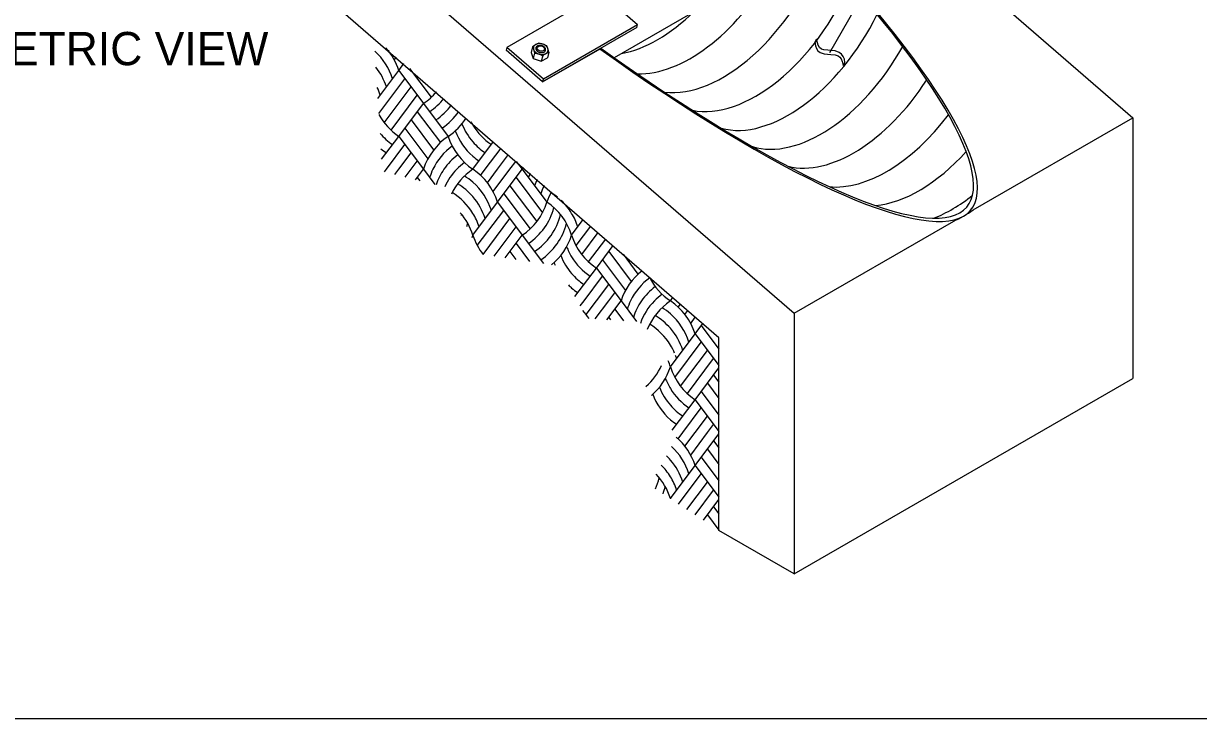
# Model space of a CAD drawing. Extents: x 99862 to 103151, y 100000 to 102076.
# Drawn here: x 101841 to 102547, y 100000 to 100418 of the extents above; entities that cross this region are included whole.
import ezdxf

# ---------------------------------------------------------------- set-up
doc = ezdxf.new("R2010")
doc.units = 0
for name, color, linetype in [('Level 1', 7, 'Continuous'), ('Level 15', 7, 'Continuous'), ('Level 20', 7, 'Continuous'), ('Level 30', 7, 'Continuous'), ('Level 9', 7, 'Continuous')]:
    doc.layers.add(name, color=color, linetype=linetype)

msp = doc.modelspace()

# ---------------------------------------------------------------- linework, layer by layer
at = {"layer": 'Level 1'}
for p, q in [((101553.78, 100893.22), (102304.36, 100243.2)), ((102259.1, 100228.52), (101542.8, 100848.86)), ((101988.26, 100810.88), (102508.01, 100360.77)), ((102296.76, 100455.02), (102196.14, 100396.92)), ((102188.14, 100435.77), (102131.57, 100403.11)), ((102210.09, 100416.76), (102188.14, 100435.77)), ((102209.66, 100415.03), (102153.09, 100382.37)), ((102210.09, 100416.76), (102153.52, 100384.1)), ((102209.66, 100415.03), (102210.09, 100416.76)), ((102131.57, 100403.11), (102131.14, 100401.38)), ((102153.09, 100382.37), (102131.14, 100401.38)), ((102153.52, 100384.1), (102131.57, 100403.11)), ((102153.09, 100382.37), (102187.6, 100402.29)), ((102153.09, 100382.37), (102153.52, 100384.1)), ((102412.04, 100305.37), (102508.01, 100360.77)), ((102508.01, 100360.77), (102508.01, 100204.01)), ((102304.36, 100243.2), (102400.33, 100298.6)), ((102304.36, 100243.2), (102304.36, 100086.43)), ((102259.1, 100112.56), (102259.1, 100228.52)), ((102304.36, 100086.43), (102508.01, 100204.01)), ((102304.36, 100086.43), (102259.1, 100112.56))]:
    msp.add_line(p, q, dxfattribs=at)
msp.add_lwpolyline([(99862, 99999.5), (103151, 99999.5), (103151, 102075.5), (99862, 102075.5)], close=True, dxfattribs=at)
for centre, major_axis, ratio, start_param, end_param in [((102135.04, 100536.62), (275.44, -231.36), 0.205372, 5.072059, 7.345323), ((102135.04, 100536.62), (273.14, -229.43), 0.205372, 5.075959, 7.341423), ((102406.18, 100380.08), (-48, -83.14), 0.57735, 0.69904, 0.871756)]:
    msp.add_ellipse(centre, major_axis=major_axis, ratio=ratio, start_param=start_param, end_param=end_param, dxfattribs=at)
at = {"layer": 'Level 15'}
msp.add_line((102325.74, 100400.11), (102401.81, 100531.87), dxfattribs=at)
at = {"layer": 'Level 20'}
for p, q in [((102316.68, 100406.19), (102317.05, 100404.07)), ((102317.74, 100408.02), (102316.69, 100406.19)), ((102318.72, 100404.46), (102317.74, 100408.02)), ((102319.6, 100403.06), (102318.72, 100404.46)), ((102060.46, 100400.86), (102060.71, 100401.2)), ((102063.9, 100395.55), (102065.21, 100397.29)), ((102317.05, 100404.07), (102317.69, 100402.42)), ((102317.69, 100402.42), (102318.65, 100401.11)), ((102318.65, 100401.11), (102319.97, 100400.11)), ((102320.68, 100402.14), (102319.6, 100403.06)), ((102319.97, 100400.11), (102322.27, 100399.22)), ((102322.08, 100401.61), (102320.68, 100402.14)), ((102324.5, 100401.41), (102322.08, 100401.61)), ((102322.27, 100399.22), (102326.35, 100398.95)), ((102328.9, 100401.03), (102324.5, 100401.41)), ((102326.35, 100398.95), (102328.89, 100398.73)), ((102328.89, 100398.73), (102330.71, 100398.09)), ((102331.45, 100400.11), (102328.9, 100401.03)), ((102330.71, 100398.09), (102331.76, 100397.27)), ((102332.85, 100399.03), (102331.45, 100400.11)), ((102331.76, 100397.27), (102332.56, 100396.18)), ((102333.87, 100397.66), (102332.85, 100399.03)), ((102334.5, 100395.99), (102333.87, 100397.66)), ((102066.58, 100389.22), (102069.7, 100393.38)), ((102073.11, 100390.41), (102086.08, 100373.11)), ((102332.56, 100396.18), (102333.18, 100394.55)), ((102333.18, 100394.55), (102333.7, 100392.19)), ((102333.7, 100392.19), (102334.76, 100394.02)), ((102334.76, 100394.02), (102334.5, 100395.99)), ((102053.99, 100372.43), (102066.58, 100389.22)), ((102054.55, 100363.29), (102070.29, 100384.27)), ((102066.58, 100389.22), (102081.43, 100369.42)), ((102057.85, 100357.78), (102074, 100379.32)), ((102061.92, 100353.32), (102077.72, 100374.37)), ((102066.58, 100349.62), (102081.43, 100369.42)), ((102081.43, 100369.42), (102096.28, 100349.62)), ((102077.72, 100364.47), (102091.62, 100345.93)), ((102074, 100359.52), (102087.55, 100341.46)), ((102056.25, 100335.85), (102066.58, 100349.62)), ((102066.58, 100349.62), (102081.43, 100329.82)), ((102070.29, 100354.57), (102084.1, 100336.16)), ((102059.15, 100329.82), (102070.29, 100344.67)), ((102111.13, 100329.82), (102123.6, 100346.46)), ((102118.55, 100329.82), (102128.1, 100342.55)), ((102066.58, 100329.82), (102074, 100339.72)), ((102074, 100329.82), (102077.72, 100334.77)), ((102125.97, 100329.82), (102132.59, 100338.64)), ((102133.4, 100329.82), (102137.08, 100334.73)), ((102137.26, 100334.58), (102140.82, 100329.82)), ((102057.96, 100328.22), (102059.15, 100329.82)), ((102064.21, 100326.66), (102066.58, 100329.82)), ((102070.46, 100325.1), (102074, 100329.82)), ((102076.71, 100323.54), (102081.43, 100329.82)), ((102081.43, 100329.82), (102088.32, 100320.63)), ((102115.78, 100326.13), (102118.55, 100329.82)), ((102119.86, 100321.67), (102125.97, 100329.82)), ((102123.3, 100316.36), (102133.4, 100329.82)), ((102125.97, 100310.02), (102140.82, 100329.82)), ((102140.82, 100329.82), (102155.67, 100310.02)), ((102077.72, 100324.87), (102079.18, 100322.92)), ((102133.4, 100319.92), (102149.56, 100298.38)), ((102137.11, 100324.87), (102153, 100303.69)), ((102129.69, 100314.97), (102145.48, 100293.92)), ((102111.13, 100290.22), (102125.97, 100310.02)), ((102125.97, 100310.02), (102140.82, 100290.22)), ((102113.8, 100283.89), (102129.69, 100305.07)), ((102117.24, 100278.58), (102133.4, 100300.12)), ((102170.52, 100290.22), (102177.51, 100299.54)), ((102123.92, 100277.58), (102137.11, 100295.17)), ((102173.2, 100283.89), (102182, 100295.63)), ((102176.64, 100278.58), (102186.49, 100291.72)), ((102130.59, 100276.59), (102140.82, 100290.22)), ((102137.11, 100285.27), (102145.27, 100274.4)), ((102140.82, 100290.22), (102153.63, 100273.16)), ((102180.72, 100274.12), (102190.99, 100287.81)), ((102133.4, 100280.33), (102136.91, 100275.64)), ((102185.37, 100270.43), (102195.48, 100283.9)), ((102192.8, 100280.33), (102206.34, 100262.27)), ((102201.41, 100278.74), (102210.41, 100266.73)), ((102172.5, 100253.27), (102185.37, 100270.43)), ((102185.37, 100270.43), (102200.22, 100250.63)), ((102189.08, 100275.38), (102202.89, 100256.96)), ((102177.95, 100250.63), (102189.08, 100265.48)), ((102185.37, 100250.63), (102192.8, 100260.53)), ((102175.68, 100247.61), (102177.95, 100250.63)), ((102179.25, 100242.47), (102185.37, 100250.63)), ((102184.68, 100239.8), (102192.8, 100250.63)), ((102191.76, 100239.35), (102200.22, 100250.63)), ((102192.8, 100250.63), (102196.51, 100255.58)), ((102200.22, 100250.63), (102209.54, 100238.2)), ((102229.92, 100250.63), (102231.42, 100252.62)), ((102234.57, 100246.93), (102235.91, 100248.71)), ((102196.51, 100245.68), (102201.74, 100238.7)), ((102238.65, 100242.47), (102240.4, 100244.8)), ((102192.8, 100240.73), (102193.94, 100239.21)), ((102242.09, 100237.16), (102244.89, 100240.89)), ((102244.77, 100230.83), (102249.38, 100236.98)), ((102248.48, 100235.78), (102259.1, 100221.61)), ((102229.92, 100211.03), (102244.77, 100230.83)), ((102244.77, 100230.83), (102259.1, 100211.71)), ((102232.59, 100204.69), (102248.48, 100225.88)), ((102236.04, 100199.39), (102252.19, 100220.93)), ((102240.11, 100194.92), (102255.9, 100215.98)), ((102244.77, 100191.23), (102259.1, 100210.35)), ((102252.19, 100201.13), (102259.1, 100191.91)), ((102255.9, 100206.08), (102259.1, 100201.81)), ((102248.48, 100196.18), (102259.1, 100182.01)), ((102230.99, 100172.85), (102244.77, 100191.23)), ((102237.34, 100171.43), (102248.48, 100186.28)), ((102244.77, 100191.23), (102259.1, 100172.11)), ((102244.77, 100171.43), (102252.19, 100181.33)), ((102234.57, 100167.74), (102237.34, 100171.43)), ((102238.65, 100163.27), (102244.77, 100171.43)), ((102242.09, 100157.97), (102252.19, 100171.43)), ((102252.19, 100171.43), (102255.9, 100176.38)), ((102244.77, 100151.63), (102259.1, 100170.75)), ((102255.9, 100166.48), (102259.1, 100162.21)), ((102252.19, 100161.53), (102259.1, 100152.31)), ((102229.92, 100131.83), (102244.77, 100151.63)), ((102244.77, 100151.63), (102259.1, 100132.52)), ((102248.48, 100156.58), (102259.1, 100142.42)), ((102234.83, 100128.49), (102248.48, 100146.68)), ((102239.81, 100125.22), (102252.19, 100141.73)), ((102244.78, 100121.96), (102255.9, 100136.78)), ((102249.76, 100118.69), (102259.1, 100131.15)), ((102252.19, 100121.93), (102259.1, 100112.72)), ((102255.9, 100126.88), (102259.1, 100122.62))]:
    msp.add_line(p, q, dxfattribs=at)
for centre, start, end in [((102030.77, 100377.83), 56.09546, 56.09634), ((102030.77, 100377.83), 56.09229, 56.09546), ((102027.06, 100372.88), 17.6434, 47.92144), ((102030.77, 100377.83), 17.6434, 41.83649), ((102023.34, 100367.93), 17.6434, 38.31474), ((102019.63, 100362.98), 17.6434, 25.40054), ((102060.47, 100400.61), 303.90361, 319.88998), ((102064.18, 100395.66), 303.90361, 321.8678), ((102087.54, 100380.81), 208.72411, 236.09639), ((102067.89, 100390.71), 303.90361, 323.8491), ((102071.6, 100385.76), 303.90361, 325.83627), ((102075.32, 100380.81), 303.90361, 327.83178), ((102139.51, 100370.91), 201.43438, 220.94161), ((102143.22, 100375.86), 207.86012, 211.33197), ((102143.22, 100375.86), 211.33188, 236.09639), ((102083.83, 100375.86), 220.57668, 236.09639), ((102117.24, 100318.43), 123.90361, 162.3566), ((102132.09, 100361.01), 197.6434, 236.09639), ((102135.8, 100365.96), 200.24322, 228.95992), ((102080.11, 100370.91), 229.78728, 236.09639), ((102120.95, 100313.48), 126.30625, 154.2266), ((102139.51, 100370.91), 220.94154, 236.09639), ((102124.66, 100308.53), 127.1006, 145.49109), ((102128.37, 100303.58), 126.331, 135.71278), ((102135.8, 100365.96), 228.95986, 236.09639), ((102120.95, 100313.48), 154.22654, 162.3566), ((102124.66, 100308.53), 145.49102, 161.50024), ((102128.37, 100303.58), 135.71269, 155.49773), ((102132.09, 100298.63), 123.90361, 154.373), ((102090.16, 100298.63), 17.6434, 56.09634), ((102176.63, 100318.43), 160.30383, 162.3566), ((102180.35, 100313.48), 158.19633, 162.3566), ((102082.74, 100288.73), 40.94134, 59.30215), ((102086.45, 100293.68), 48.95968, 58.54646), ((102086.45, 100293.68), 17.6434, 48.95975), ((102184.06, 100308.53), 156.1156, 162.3566), ((102187.77, 100303.58), 154.05795, 162.3566), ((102079.03, 100283.78), 31.33163, 58.48737), ((102082.74, 100288.73), 17.6434, 40.94141), ((102191.48, 100298.63), 152.02004, 162.3566), ((102138.42, 100283.78), 51.29645, 58.48737), ((102119.86, 100321.41), 303.90361, 342.3566), ((102123.58, 100316.46), 303.90361, 345.01126), ((102134.71, 100278.84), 17.6434, 56.09639), ((102138.42, 100283.78), 31.33163, 46.63234), ((102075.32, 100278.84), 17.6434, 41.28523), ((102067.89, 100311.51), 345.51092, 346.31988), ((102079.03, 100283.78), 17.6434, 31.33172), ((102127.29, 100311.51), 303.90361, 346.31988), ((102138.42, 100283.78), 17.6434, 31.33172), ((102071.6, 100306.56), 342.67112, 345.77133), ((102131, 100306.56), 303.90361, 345.77133), ((102075.32, 100301.61), 339.97622, 342.3566), ((102146.94, 100301.61), 197.64354, 217.81866), ((102134.71, 100301.61), 309.08024, 342.3566), ((102206.33, 100301.61), 197.64354, 236.09639), ((102198.91, 100291.71), 201.43438, 220.94161), ((102202.62, 100296.66), 200.87781, 211.33197), ((102202.62, 100296.66), 211.33188, 236.09639), ((102195.2, 100286.76), 200.24322, 202.94034), ((102198.91, 100291.71), 220.94154, 236.09639), ((102236.03, 100239.24), 128.12232, 162.3566), ((102239.74, 100234.29), 126.30625, 154.2266), ((102250.88, 100281.81), 206.78548, 236.09639), ((102195.2, 100286.76), 224.90332, 228.95992), ((102195.19, 100286.76), 228.95986, 236.09639), ((102243.45, 100229.34), 127.1006, 145.49109), ((102239.74, 100234.29), 154.22654, 162.3566), ((102243.45, 100229.34), 145.49102, 162.3566), ((102247.17, 100224.39), 135.71269, 160.14728), ((102250.88, 100219.44), 123.90361, 158.03778), ((102247.17, 100224.39), 126.331, 135.71278), ((102208.96, 100219.44), 17.6434, 56.09634), ((102149.56, 100219.44), 33.2494, 42.59671), ((102201.53, 100209.54), 40.94134, 59.30215), ((102205.25, 100214.49), 48.95968, 58.54646), ((102205.24, 100214.49), 17.6434, 48.95975), ((102197.82, 100204.59), 31.33163, 58.48737), ((102201.53, 100209.54), 17.6434, 40.94141), ((102197.82, 100204.59), 22.93575, 31.33172), ((102194.11, 100199.64), 17.6434, 23.58804), ((102197.82, 100204.59), 17.6434, 20.65552), ((102190.4, 100227.37), 311.32441, 335.66285), ((102194.11, 100222.42), 310.33908, 342.3566), ((102265.73, 100222.42), 197.64354, 236.09639), ((102262.02, 100217.47), 200.87781, 211.33197), ((102254.59, 100207.57), 200.24322, 228.95992), ((102258.3, 100212.52), 201.43438, 220.94161), ((102262.01, 100217.47), 211.33188, 236.09639), ((102258.3, 100212.52), 220.94154, 236.09639), ((102254.59, 100207.57), 228.95986, 236.09639), ((102208.96, 100140.24), 17.6434, 49.3061), ((102201.53, 100130.34), 40.94134, 46.36292), ((102205.24, 100135.29), 17.6434, 47.71239), ((102197.82, 100125.39), 31.33163, 45.00368), ((102201.53, 100130.34), 17.6434, 40.94141), ((102186.68, 100153.12), 335.63908, 346.31988), ((102194.11, 100120.44), 17.6434, 43.63506), ((102197.82, 100125.39), 17.6434, 31.33172), ((102190.4, 100148.17), 338.89825, 345.77133), ((102194.11, 100143.22), 342.19797, 342.3566), ((102265.73, 100143.22), 197.64354, 197.88516)]:
    msp.add_arc(centre, 37.58, start, end, dxfattribs=at)
at = {"layer": 'Level 30'}
for centre, start_param, end_param in [((102261.61, 100463.55), 0.240997, 1.861824), ((102241.95, 100474.9), 0.295282, 1.581599), ((102281.26, 100452.2), 0.189709, 1.777637), ((102222.29, 100486.25), 0.458261, 1.112535), ((102300.92, 100440.85), 0.147068, 1.688457), ((102320.58, 100429.5), 0.129366, 1.592402), ((102340.24, 100418.15), 0.163481, 1.486404), ((102359.9, 100406.8), 0.251886, 1.364723), ((102379.56, 100395.45), 0.387379, 1.21369), ((102399.22, 100384.1), 0.624125, 0.968572)]:
    msp.add_ellipse(centre, major_axis=(-48, -83.14), ratio=0.57735, start_param=start_param, end_param=end_param, dxfattribs=at)
at = {"layer": 'Level 9'}
for p, q in [((102146.94, 100403.48), (102146.1, 100400.12)), ((102146.1, 100400.12), (102147.35, 100396.38)), ((102148.18, 100399.74), (102147.35, 100396.38)), ((102147.61, 100401.95), (102147.65, 100401.82)), ((102150.6, 100399.25), (102150.83, 100399.18)), ((102153.11, 100398.13), (102152.28, 100394.77)), ((102154.93, 100399.42), (102155.09, 100399.51)), ((102156.78, 100400.25), (102155.95, 100396.89)), ((102147.35, 100396.38), (102152.28, 100394.77)), ((102152.28, 100394.77), (102155.95, 100396.89))]:
    msp.add_line(p, q, dxfattribs=at)
for major_axis, start_param, end_param in [((4.37, -1.08), 2.512579, 3.538887), ((4.37, -1.08), 0.431368, 2.512579), ((4.37, -1.08), 3.580667, 4.579733), ((-2.91, 0.72), 5.654172, 6.714441), ((4.37, -1.08), 4.634216, 5.629445), ((4.37, -1.08), 5.678899, 6.68814)]:
    msp.add_ellipse((102151.93, 100402.14), major_axis=major_axis, ratio=0.700141, start_param=start_param, end_param=end_param, dxfattribs=at)
msp.add_ellipse((102151.99, 100402.43), major_axis=(2.21, -0.55), ratio=0.700141, dxfattribs=at)
for points, degree in [([(102146.94, 100403.48), (102147.09, 100403.6), (102147.24, 100403.72), (102147.39, 100403.83), (102147.88, 100404.21), (102148.37, 100404.54), (102148.84, 100404.82)], 3), ([(102148.84, 100404.82), (102149, 100404.91), (102149.15, 100404.99), (102149.31, 100405.07), (102149.76, 100405.3), (102150.19, 100405.47), (102150.61, 100405.6)], 3), ([(102154.88, 100401.91), (102154.9, 100401.67), (102154.86, 100401.43), (102154.77, 100401.21), (102154.68, 100400.99), (102154.54, 100400.79), (102154.34, 100400.62), (102154.15, 100400.45), (102153.92, 100400.3), (102153.65, 100400.2), (102153.38, 100400.09), (102153.07, 100400.02), (102152.75, 100400), (102152.44, 100399.97), (102152.1, 100399.98), (102151.77, 100400.03), (102151.44, 100400.09), (102151.11, 100400.18), (102150.8, 100400.31), (102150.49, 100400.44), (102150.21, 100400.61), (102149.96, 100400.8), (102149.71, 100400.98), (102149.5, 100401.2), (102149.34, 100401.43), (102149.18, 100401.66), (102149.07, 100401.9), (102149.01, 100402.15), (102148.96, 100402.39), (102148.96, 100402.63), (102149.01, 100402.86), (102149.07, 100403.09), (102149.18, 100403.31), (102149.34, 100403.5), (102149.51, 100403.68), (102149.72, 100403.85), (102149.97, 100403.98), (102150.21, 100404.11), (102150.5, 100404.2), (102150.81, 100404.25), (102151.11, 100404.3), (102151.45, 100404.32), (102151.78, 100404.29), (102152.11, 100404.26), (102152.44, 100404.19), (102152.76, 100404.08), (102153.08, 100403.98), (102153.38, 100403.83), (102153.65, 100403.66), (102153.92, 100403.49), (102154.16, 100403.28), (102154.35, 100403.06), (102154.54, 100402.85), (102154.68, 100402.61), (102154.77, 100402.37), (102154.83, 100402.21), (102154.86, 100402.06), (102154.88, 100401.91)], 3), ([(102155.53, 100403.98), (102154.72, 100404.44), (102153.86, 100404.85), (102152.97, 100405.12), (102152.19, 100405.36), (102151.39, 100405.51), (102150.61, 100405.6)], 3), ([(102146.94, 100403.48), (102147.17, 100403.06), (102147.4, 100402.56), (102147.61, 100401.95)], 2), ([(102147.65, 100401.82), (102147.66, 100401.8), (102147.67, 100401.78), (102147.67, 100401.76), (102147.87, 100401.16), (102148.03, 100400.46), (102148.18, 100399.74)], 3), ([(102148.18, 100399.74), (102148.99, 100399.65), (102149.81, 100399.5), (102150.6, 100399.25)], 2), ([(102150.83, 100399.18), (102150.85, 100399.17), (102150.87, 100399.16), (102150.89, 100399.16), (102151.66, 100398.89), (102152.4, 100398.53), (102153.11, 100398.13)], 3), ([(102153.11, 100398.13), (102153.26, 100398.25), (102153.41, 100398.37), (102153.56, 100398.49), (102154.02, 100398.84), (102154.49, 100399.16), (102154.93, 100399.42)], 3), ([(102155.09, 100399.51), (102155.22, 100399.59), (102155.35, 100399.66), (102155.48, 100399.72), (102155.93, 100399.95), (102156.37, 100400.12), (102156.78, 100400.25)], 3), ([(102156.21, 100402.44), (102156.2, 100402.47), (102156.19, 100402.5), (102156.18, 100402.52), (102155.98, 100403.1), (102155.76, 100403.58), (102155.53, 100403.98)], 3), ([(102156.78, 100400.25), (102156.62, 100401.01), (102156.45, 100401.73), (102156.24, 100402.35)], 2)]:
    msp.add_open_spline(points, degree=degree, dxfattribs=at)

# ---------------------------------------------------------------- texts
at = {"layer": 'Level 20'}
msp.add_text('ISOMETRIC VIEW', height=20, dxfattribs=at).set_placement((101763.79, 100392.41))

doc.saveas('drawing.dxf')
